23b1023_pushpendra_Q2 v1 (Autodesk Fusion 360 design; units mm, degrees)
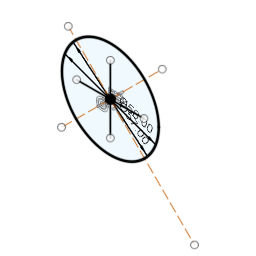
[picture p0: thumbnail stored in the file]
sketch "Sketch1" plane through (0, 0, 0) normal (0, 1, 0) x axis (1, 0, 0)
  line L1 (20, 0) -> (0, 0)
  line L2 (0, 20) -> (0, 0)
  line L3 (0, -20) -> (0, 0)
  line L4 (-20, 0) -> (0, 0)
  line L5 (30.8315, -30.8579) -> (0, 0)
  line L6 (-29.0129, 28.9865) -> (0, 0)
  line L7 (50, 50) -> (0, 0)
  line L8 (-25, -25) -> (0, 0)
  circle C1 centre (0, 0) radius 28.5
  circle C2 centre (0, 0) radius 29
  point P1 (0, 0)
  point P2 (0, 0)
  point P4 (0, 0)
  point P3 (0, 0)
  point P6 (0, 0)
  point P8 (0, 0)
  point P10 (0, 0)
  point P12 (0, 0)
  point P14 (0, 0)
  point P16 (0, 0)
  point P18 (0, 0)
  coincident P1 P2
  concentric C1 C2
  coincident P2 P4
  horizontal L1
  coincident P3 P6
  perpendicular L1 L2
  coincident P1 P8
  perpendicular L1 L3
  coincident P2 P10
  perpendicular L2 L4
  coincident P1 P12
  coincident P3 P14
  coincident P1 P16
  coincident P1 P18
  dimension "d1" diameter C1 = 57
  dimension "d2" diameter C2 = 58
